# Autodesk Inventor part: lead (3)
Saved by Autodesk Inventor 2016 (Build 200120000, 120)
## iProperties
Created: 2016-09
Part Number: lead (3)
Material: Generic
Document SubType Name: Modeling
Designer: Administrator
Appearance: Generic
Author: Administrator
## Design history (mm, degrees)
feature "Body1"
body "Solid1"
